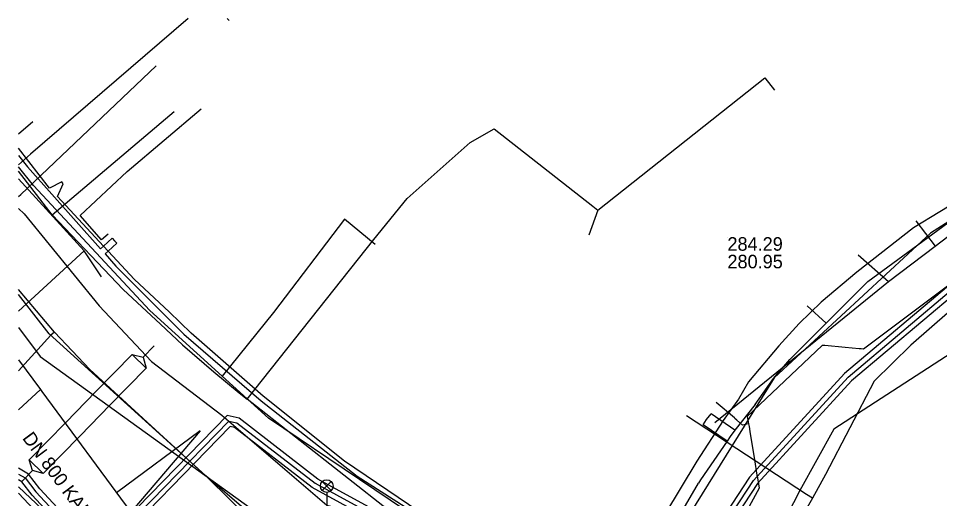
# Model space of a CAD drawing. Extents: x -599854 to -599675, y -1160809 to -1160543.
# Drawn here: x -599854.4 to -599799.9, y -1160572.3 to -1160543.9 of the extents above; entities that cross this region are included whole.
import ezdxf

# ---------------------------------------------------------------- set-up
doc = ezdxf.new("R2010")
doc.units = 0
for name, color, linetype in [('BKOM-ODVODNENI_trasa sítě', 7, 'Continuous'), ('BVK-JEDNOTNA_popisy', 7, 'Continuous'), ('BVK-JEDNOTNA_trasa sítě', 7, 'Continuous'), ('BVK-KANALIZACE_ vyřazená trasa sítě', 7, 'Continuous'), ('BVK-VODOVOD_trasa sítě', 7, 'Continuous'), ('BVK-VODOVOD_trasa zrušené sítě', 7, 'Continuous'), ('CETIN_kabel podzemní', 7, 'Continuous'), ('CETIN_kabel podzemní neprovozovaný', 7, 'Continuous'), ('DESTOVA_trasa neprovozované sítě', 7, 'Continuous'), ('DPMB_kabel', 7, 'Continuous'), ('DPMB_kyneta', 7, 'Continuous'), ('DPMB_trolejové vedení-nosné lano', 7, 'Continuous'), ('DSP-DESTOVA-BVK_trasa podzemní sítě', 7, 'Continuous'), ('EON-NN_kabel', 7, 'Continuous'), ('EON-NN_kabel zrušené sítě', 7, 'Continuous'), ('INNOGY-NTL_trasa sítě', 7, 'Continuous'), ('INNOGY-STL_trasa sítě', 7, 'Continuous'), ('JEDNOTNA-NEPR_popisy', 7, 'Continuous'), ('JEDNOTNA_trasa neprovozované sítě', 7, 'Continuous'), ('SPLASKOVA_neprovozovaná  trasa sítě', 7, 'Continuous'), ('TSB_kabel VO', 7, 'Continuous'), ('TSB_lampy VO', 7, 'Continuous')]:
    doc.layers.add(name, color=color, linetype=linetype)

msp = doc.modelspace()

# ---------------------------------------------------------------- linework, layer by layer
at = {"layer": 'BKOM-ODVODNENI_trasa sítě'}
msp.add_lwpolyline([(-599843.62, -1160568.32), (-599848.57, -1160571.983)], dxfattribs=at)
at = {"layer": 'BVK-JEDNOTNA_trasa sítě'}
msp.add_lwpolyline([(-599854.3744, -1160564.1398), (-599853.077, -1160565.893), (-599852.994, -1160566.006), (-599847.723, -1160573.128), (-599844.85, -1160577.01)], dxfattribs=at)
at = {"layer": 'BVK-KANALIZACE_ vyřazená trasa sítě'}
for p, q in [((-599854.3744, -1160562.2158), (-599853.08, -1160563.93)), ((-599853.08, -1160563.93), (-599822.796, -1160585.73))]:
    msp.add_line(p, q, dxfattribs=at)
at = {"layer": 'BVK-VODOVOD_trasa sítě'}
for points in [[(-599854.3744, -1160554.484), (-599854.23, -1160554.35), (-599846.229, -1160546.757)], [(-599773.52, -1160553.4), (-599779.95, -1160553.74), (-599785.89, -1160554.08), (-599789.37, -1160554.47), (-599792.01, -1160555.84), (-599793.4, -1160556.58), (-599795.21, -1160557.59), (-599797.11, -1160559.34), (-599801.61, -1160563.26), (-599803.76, -1160565.39), (-599806.64, -1160570.9), (-599807.42, -1160572.3), (-599808.48, -1160574.16), (-599810.38, -1160577.75), (-599811.83, -1160580.4), (-599815.36, -1160586.95)], [(-599843.3, -1160570.99), (-599845.79, -1160568.7), (-599850.15, -1160564.7), (-599852.25, -1160562.49), (-599854.3744, -1160559.9757)], [(-599852.25, -1160562.49), (-599852.45, -1160562.67), (-599854.3744, -1160564.7743)], [(-599807.42, -1160572.3), (-599807.77, -1160572.09), (-599814.866, -1160567.431)], [(-599815.98, -1160587.08), (-599816.39, -1160586.87), (-599822, -1160583.72), (-599827.25, -1160580.9), (-599830.01, -1160579.46), (-599835.52, -1160576.6), (-599838.52, -1160575.08), (-599843.3, -1160570.99)]]:
    msp.add_lwpolyline(points, dxfattribs=at)
at = {"layer": 'BVK-VODOVOD_trasa zrušené sítě'}
for points in [[(-599723.312, -1160596.189), (-599723.552, -1160595.075), (-599725.385, -1160585.124), (-599727.088, -1160577.648), (-599730.061, -1160573.561), (-599730.185, -1160573.396), (-599730.663, -1160572.731), (-599734.747, -1160567.144), (-599747.147, -1160556.314), (-599750.794, -1160554.698), (-599754.863, -1160552.892), (-599773.118, -1160554.584), (-599787.156, -1160555.886), (-599789.075, -1160557.142), (-599798.149, -1160563.04), (-599806.144, -1160568.237), (-599808.168, -1160571.846), (-599815.66, -1160586.425), (-599816.228, -1160587.481)], [(-599843.3, -1160570.99), (-599852.563, -1160562.601), (-599854.3744, -1160560.2608)], [(-599827.89, -1160581.85), (-599830.538, -1160580.457), (-599838.842, -1160575.375), (-599843.3, -1160570.99)]]:
    msp.add_lwpolyline(points, dxfattribs=at)
at = {"layer": 'CETIN_kabel podzemní'}
for points in [[(-599820.11, -1160555.29), (-599810.24, -1160547.46), (-599809.67, -1160548.18)], [(-599760.54, -1160548.25), (-599763.79, -1160549.79), (-599775.39, -1160551.91), (-599776.73, -1160551.13), (-599777.24, -1160548.01), (-599779.6, -1160547.75), (-599787.47, -1160549.87), (-599795.94, -1160553.78), (-599800.44, -1160556.65), (-599809.68, -1160565.19), (-599817.48, -1160577.77), (-599818.39, -1160579.19)], [(-599852.38, -1160555.55), (-599845.17, -1160549.46)], [(-599840.85, -1160566.46), (-599833.35, -1160557.02), (-599831.38, -1160554.59), (-599827.65, -1160551.29), (-599826.25, -1160550.48), (-599820.41, -1160555.05)], [(-599852.38, -1160555.55), (-599854.3744, -1160552.9779)], [(-599820.11, -1160555.29), (-599820.64, -1160556.77)], [(-599820.41, -1160555.05), (-599820.11, -1160555.29)], [(-599852.38, -1160555.55), (-599848.19, -1160559.97), (-599845.98, -1160562.03), (-599844.68, -1160563.25), (-599842.81, -1160564.83), (-599841.32, -1160566.09), (-599840.85, -1160566.46)], [(-599823.44, -1160578.45), (-599824.88, -1160577.95), (-599832.27, -1160573.2), (-599840.85, -1160566.46)], [(-599854.3744, -1160571.6429), (-599849.83, -1160575.91)], [(-599843.04, -1160581.78), (-599843.38, -1160581.56), (-599846.12, -1160579.58), (-599852.83, -1160573.64), (-599854.3744, -1160572.0135)]]:
    msp.add_lwpolyline(points, dxfattribs=at)
at = {"layer": 'CETIN_kabel podzemní neprovozovaný'}
for points in [[(-599806.6, -1160561.96), (-599804.15, -1160559.5), (-599797.63, -1160554.73), (-599791.29, -1160551.62), (-599785.97, -1160549.54)], [(-599842.33, -1160565.09), (-599846.61, -1160561.22), (-599853.48, -1160553.82), (-599854.3744, -1160552.713)], [(-599833.282, -1160557.31), (-599835.1, -1160555.81), (-599839.29, -1160561.34), (-599842.33, -1160565.09)], [(-599807.73, -1160560.93), (-599806.6, -1160561.96)], [(-599807.4, -1160562.76), (-599806.6, -1160561.96)], [(-599810.81, -1160566.78), (-599809.72, -1160565.24), (-599808.75, -1160564.12), (-599807.4, -1160562.76)], [(-599823.44, -1160578.45), (-599839.59, -1160567.57), (-599842.33, -1160565.09)], [(-599810.81, -1160566.78), (-599812, -1160568.29)], [(-599812.47, -1160568.93), (-599813.88, -1160567.97), (-599813.68, -1160567.65), (-599813.41, -1160567.33)], [(-599812, -1160568.29), (-599813.41, -1160567.33)], [(-599812, -1160568.29), (-599812.29, -1160568.67), (-599812.47, -1160568.93)], [(-599812.47, -1160568.93), (-599814.03, -1160571.22), (-599814.15, -1160571.42)], [(-599818.09, -1160578.47), (-599817.64, -1160577.42), (-599814.15, -1160571.42)]]:
    msp.add_lwpolyline(points, dxfattribs=at)
at = {"layer": 'DESTOVA_trasa neprovozované sítě'}
for p, q in [((-599801.31, -1160555.91), (-599800.171, -1160557.403)), ((-599813.2, -1160567.84), (-599802.92, -1160559.49)), ((-599843.62, -1160568.32), (-599847.723, -1160573.128))]:
    msp.add_line(p, q, dxfattribs=at)
at = {"layer": 'DPMB_kabel'}
for points in [[(-599854.3744, -1160570.8811), (-599853.98, -1160571.11), (-599853.34, -1160571.94), (-599850.41, -1160575.09), (-599849.54, -1160575.55), (-599841.94, -1160567.75), (-599841.46, -1160567.86), (-599836.83, -1160571.43), (-599830.31, -1160574.99), (-599826.68, -1160574.81), (-599821.59, -1160577.6), (-599817.92, -1160579.72), (-599816.48, -1160579.55), (-599815.751, -1160578.652), (-599810.91, -1160571.26), (-599805.31, -1160565.16), (-599798.95, -1160559.8), (-599795.69, -1160558.33), (-599784.88, -1160555), (-599775.62, -1160554.42), (-599765.57, -1160554.12), (-599753.796, -1160555.833), (-599746.11, -1160559.64), (-599743.15, -1160562.7)], [(-599854.3744, -1160570.8811), (-599853.98, -1160571.11), (-599853.34, -1160571.94), (-599850.41, -1160575.09), (-599849.54, -1160575.55), (-599841.94, -1160567.75), (-599841.46, -1160567.86), (-599836.83, -1160571.43), (-599830.31, -1160574.99), (-599826.68, -1160574.81), (-599821.59, -1160577.6), (-599817.92, -1160579.72), (-599816.48, -1160579.55), (-599815.751, -1160578.652), (-599810.91, -1160571.26), (-599805.31, -1160565.16), (-599798.95, -1160559.8), (-599795.69, -1160558.33), (-599784.88, -1160555), (-599775.62, -1160554.42), (-599765.57, -1160554.12), (-599753.796, -1160555.833), (-599746.11, -1160559.64), (-599743.15, -1160562.7)], [(-599799.111, -1160559.544), (-599805.518, -1160564.943), (-599811.148, -1160571.075), (-599815.994, -1160578.475), (-599816.636, -1160579.266), (-599817.856, -1160579.41), (-599821.443, -1160577.339), (-599826.61, -1160574.506), (-599830.24, -1160574.686), (-599836.666, -1160571.178), (-599841.329, -1160567.582), (-599842.037, -1160567.42), (-599849.598, -1160575.18), (-599850.225, -1160574.849), (-599853.111, -1160571.746), (-599853.778, -1160570.88), (-599854.3744, -1160570.5339)], [(-599799.111, -1160559.544), (-599805.518, -1160564.943), (-599811.148, -1160571.075), (-599815.994, -1160578.475), (-599816.636, -1160579.266), (-599817.856, -1160579.41), (-599821.443, -1160577.339), (-599826.61, -1160574.506), (-599830.24, -1160574.686), (-599836.666, -1160571.178), (-599841.329, -1160567.582), (-599842.037, -1160567.42), (-599849.598, -1160575.18), (-599850.225, -1160574.849), (-599853.111, -1160571.746), (-599853.778, -1160570.88), (-599854.3744, -1160570.5339)]]:
    msp.add_lwpolyline(points, dxfattribs=at)
at = {"layer": 'DPMB_kyneta'}
msp.add_lwpolyline([(-599775.601, -1160554.719), (-599784.826, -1160555.297), (-599795.584, -1160558.611), (-599798.789, -1160560.056), (-599805.102, -1160565.377), (-599810.672, -1160571.445), (-599815.508, -1160578.829), (-599816.324, -1160579.834), (-599817.984, -1160580.03), (-599821.737, -1160577.861), (-599826.75, -1160575.114), (-599830.38, -1160575.294), (-599836.994, -1160571.682), (-599841.591, -1160568.138), (-599841.843, -1160568.08), (-599849.482, -1160575.92), (-599850.595, -1160575.331), (-599853.569, -1160572.134), (-599854.182, -1160571.34), (-599854.3744, -1160571.2283)], dxfattribs=at)
at = {"layer": 'DPMB_trolejové vedení-nosné lano'}
for points in [[(-599846.34, -1160563.31), (-599846.995, -1160563.979)], [(-599849.79, -1160566.01), (-599847.64, -1160563.812)], [(-599846.814, -1160564.621), (-599847.64, -1160563.812), (-599846.995, -1160563.979), (-599846.814, -1160564.621)], [(-599848.94, -1160566.79), (-599846.814, -1160564.621)], [(-599851.57, -1160567.83), (-599849.79, -1160566.01)], [(-599850.73, -1160568.62), (-599848.94, -1160566.79)], [(-599853.73, -1160570.033), (-599851.57, -1160567.83)], [(-599852.904, -1160570.842), (-599850.73, -1160568.62)], [(-599853.73, -1160570.033), (-599852.904, -1160570.842), (-599853.549, -1160570.675), (-599853.73, -1160570.033)], [(-599853.549, -1160570.675), (-599854.16, -1160571.3)]]:
    msp.add_lwpolyline(points, dxfattribs=at)
at = {"layer": 'DSP-DESTOVA-BVK_trasa podzemní sítě'}
msp.add_line((-599843.62, -1160568.32), (-599848.57, -1160571.983), dxfattribs=at)
at = {"layer": 'EON-NN_kabel'}
for points in [[(-599851.817, -1160553.617), (-599852.543, -1160553.983), (-599854.3744, -1160551.6276)], [(-599821.363, -1160575.54), (-599823.141, -1160577.829), (-599827.207, -1160575.361), (-599828.753, -1160574.423), (-599835.09, -1160570.128), (-599839.903, -1160566.27), (-599844.158, -1160562.552), (-599845.457, -1160561.284), (-599847.509, -1160559.388), (-599849.071, -1160557.708), (-599849.343, -1160557.415), (-599852.072, -1160554.48), (-599851.727, -1160553.718), (-599851.817, -1160553.617)], [(-599796.78, -1160553.49), (-599801.45, -1160556.33), (-599804.8, -1160558.95), (-599806.9, -1160560.72), (-599808.2, -1160561.99), (-599809.4, -1160563.31), (-599811.2, -1160565.43), (-599811.8, -1160566.46), (-599812.69, -1160567.72), (-599814.26, -1160570.12), (-599817.09, -1160574.82), (-599818.695, -1160577.517), (-599818.81, -1160577.71), (-599819.13, -1160578.07), (-599819.44, -1160578.07), (-599820.432, -1160577.383), (-599821.126, -1160576.901), (-599821.2, -1160576.85), (-599821.285, -1160576.478), (-599821.33, -1160576.28), (-599821.329, -1160576.276), (-599821.173, -1160575.723), (-599821.15, -1160575.64)]]:
    msp.add_lwpolyline(points, dxfattribs=at)
at = {"layer": 'EON-NN_kabel zrušené sítě'}
for points in [[(-599849.075, -1160556.711), (-599849.452, -1160557.04), (-599850.72, -1160555.598), (-599847.943, -1160553.005), (-599843.572, -1160549.298)], [(-599854.3744, -1160552.0569), (-599853.835, -1160552.73), (-599849.517, -1160557.574), (-599849.343, -1160557.415), (-599848.83, -1160556.948), (-599848.695, -1160557.095), (-599848.56, -1160557.243), (-599849.071, -1160557.708), (-599849.251, -1160557.872), (-599848.608, -1160558.593), (-599844.591, -1160562.612), (-599840.011, -1160566.554), (-599834.335, -1160571.008), (-599828.888, -1160574.494), (-599827.207, -1160575.361), (-599822.963, -1160577.551), (-599821.799, -1160575.81), (-599821.244, -1160575.265)]]:
    msp.add_lwpolyline(points, dxfattribs=at)
at = {"layer": 'INNOGY-NTL_trasa sítě'}
for points in [[(-599844.3422, -1160543.9495), (-599853.66, -1160551.98), (-599854.3744, -1160552.5941)], [(-599841.92, -1160544.08), (-599842.033, -1160543.9495)], [(-599849.46, -1160559.23), (-599850.48, -1160557.69), (-599854.3744, -1160553.426)], [(-599850.48, -1160557.69), (-599854.3744, -1160561.2448)]]:
    msp.add_lwpolyline(points, dxfattribs=at)
at = {"layer": 'INNOGY-STL_trasa sítě'}
for points in [[(-599780.99, -1160552.44), (-599791.78, -1160554.03), (-599792.31, -1160554.45), (-599794.05, -1160555.73), (-599804.4, -1160563.49), (-599804.53, -1160563.48), (-599804.66, -1160563.47), (-599805.49, -1160563.4), (-599806.68, -1160563.29), (-599806.84, -1160563.28), (-599811.27, -1160567.47), (-599811.2, -1160567.91), (-599811.17, -1160568.07), (-599811.12, -1160568.36), (-599810.84, -1160570.05), (-599810.7, -1160570.94), (-599810.69, -1160571.01), (-599810.61, -1160571.46), (-599810.57, -1160571.72), (-599813.95, -1160577.93), (-599814.51, -1160578.96)], [(-599811.2, -1160567.91), (-599811.56, -1160567.99), (-599811.89, -1160567.69), (-599812, -1160567.59), (-599812.03, -1160567.56), (-599813.11, -1160566.65)]]:
    msp.add_lwpolyline(points, dxfattribs=at)
at = {"layer": 'JEDNOTNA-NEPR_popisy'}
msp.add_line((-599812.445, -1160556.88), (-599812.445, -1160556.88), dxfattribs=at)
at = {"layer": 'JEDNOTNA_trasa neprovozované sítě'}
for p, q in [((-599804.71, -1160557.92), (-599802.92, -1160559.49)), ((-599854.3744, -1160567.0907), (-599853.077, -1160565.893))]:
    msp.add_line(p, q, dxfattribs=at)
msp.add_lwpolyline([(-599802.92, -1160559.49), (-599800.171, -1160557.403), (-599795.07, -1160553.53), (-599787.61, -1160550.66)], dxfattribs=at)
at = {"layer": 'SPLASKOVA_neprovozovaná  trasa sítě'}
msp.add_line((-599853.518, -1160550.071), (-599854.3744, -1160550.7855), dxfattribs=at)
at = {"layer": 'TSB_kabel VO'}
msp.add_lwpolyline([(-599854.3744, -1160555.1902), (-599854.04, -1160555.5), (-599849.6, -1160560.93), (-599846.5, -1160564.23), (-599842.34, -1160567.41), (-599836.14, -1160572.72), (-599835.53, -1160572.87), (-599830.9, -1160574.94), (-599826.66, -1160576.79), (-599812.72, -1160583.91), (-599805.44, -1160587.49), (-599799.47, -1160590.02), (-599798.76, -1160590.06), (-599794.55, -1160590.16), (-599791.05, -1160588.25), (-599791.37, -1160587.42), (-599790.5, -1160586.88), (-599785.83, -1160583.3), (-599779.31, -1160578.94), (-599776.23, -1160575.89), (-599774.72, -1160572.96), (-599774.64, -1160569.54), (-599766.89, -1160569.33), (-599766.71, -1160568.47)], dxfattribs=at)
at = {"layer": 'TSB_lampy VO'}
for p, q in [((-599836.405, -1160571.86), (-599835.875, -1160571.33)), ((-599836.405, -1160571.33), (-599835.875, -1160571.86)), ((-599836.405, -1160571.86), (-599835.875, -1160571.33)), ((-599836.405, -1160571.33), (-599835.875, -1160571.86)), ((-599836.14, -1160571.97), (-599836.14, -1160572.72)), ((-599836.14, -1160571.97), (-599836.14, -1160572.72))]:
    msp.add_line(p, q, dxfattribs=at)
msp.add_circle((-599836.14, -1160571.595), 0.375, dxfattribs=at)
msp.add_circle((-599836.14, -1160571.595), 0.375, dxfattribs=at)

# ---------------------------------------------------------------- texts
at = {"layer": 'BVK-JEDNOTNA_popisy'}
msp.add_text('DN 800 KAM', height=0.8, rotation=306.50404, dxfattribs=at).set_placement((-599854.175, -1160568.766))
at = {"layer": 'JEDNOTNA-NEPR_popisy'}
for s, p in [('284.29', (-599812.445, -1160557.68)), ('280.95', (-599812.445, -1160558.72))]:
    msp.add_text(s, height=0.8, dxfattribs=at).set_placement(p)

doc.saveas('drawing.dxf')
